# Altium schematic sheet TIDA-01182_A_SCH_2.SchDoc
size 431 x 279 mm; Date: Not shown in title block; ApprovedBy: Not shown in title block; CheckedBy: Not shown in title block; Author: Not shown in title block; CompanyName: Not shown in title block; DrawnBy: Gordon Varney; Engineer: Not shown in title block; Organization: Not shown in title block; Address1: Not shown in title block; Address2: Not shown in title block; Address3: Not shown in title block; Address4: Not shown in title block; DocumentNumber: 1; Revision: Use project parameter SCH_Rev; SheetNumber: 3; SheetTotal: 4; PageSetup: Record=PageOptions¦CenterHorizontal=True¦CenterVertical=True¦PrintScale=0.66¦XCorrection=1.00¦YCorrection=1.00¦PrintKind=0¦BorderSize=5000000¦LeftOffset=0¦BottomOffset=0¦Orientation=2¦PaperLength=1000¦PaperWidth=1000¦Scale=100¦PaperSource=15¦PrintQuality=1200¦MediaType=1¦DitherType=10¦PrintScaleMode=1¦PaperKind=Letter¦PaperIndex=1
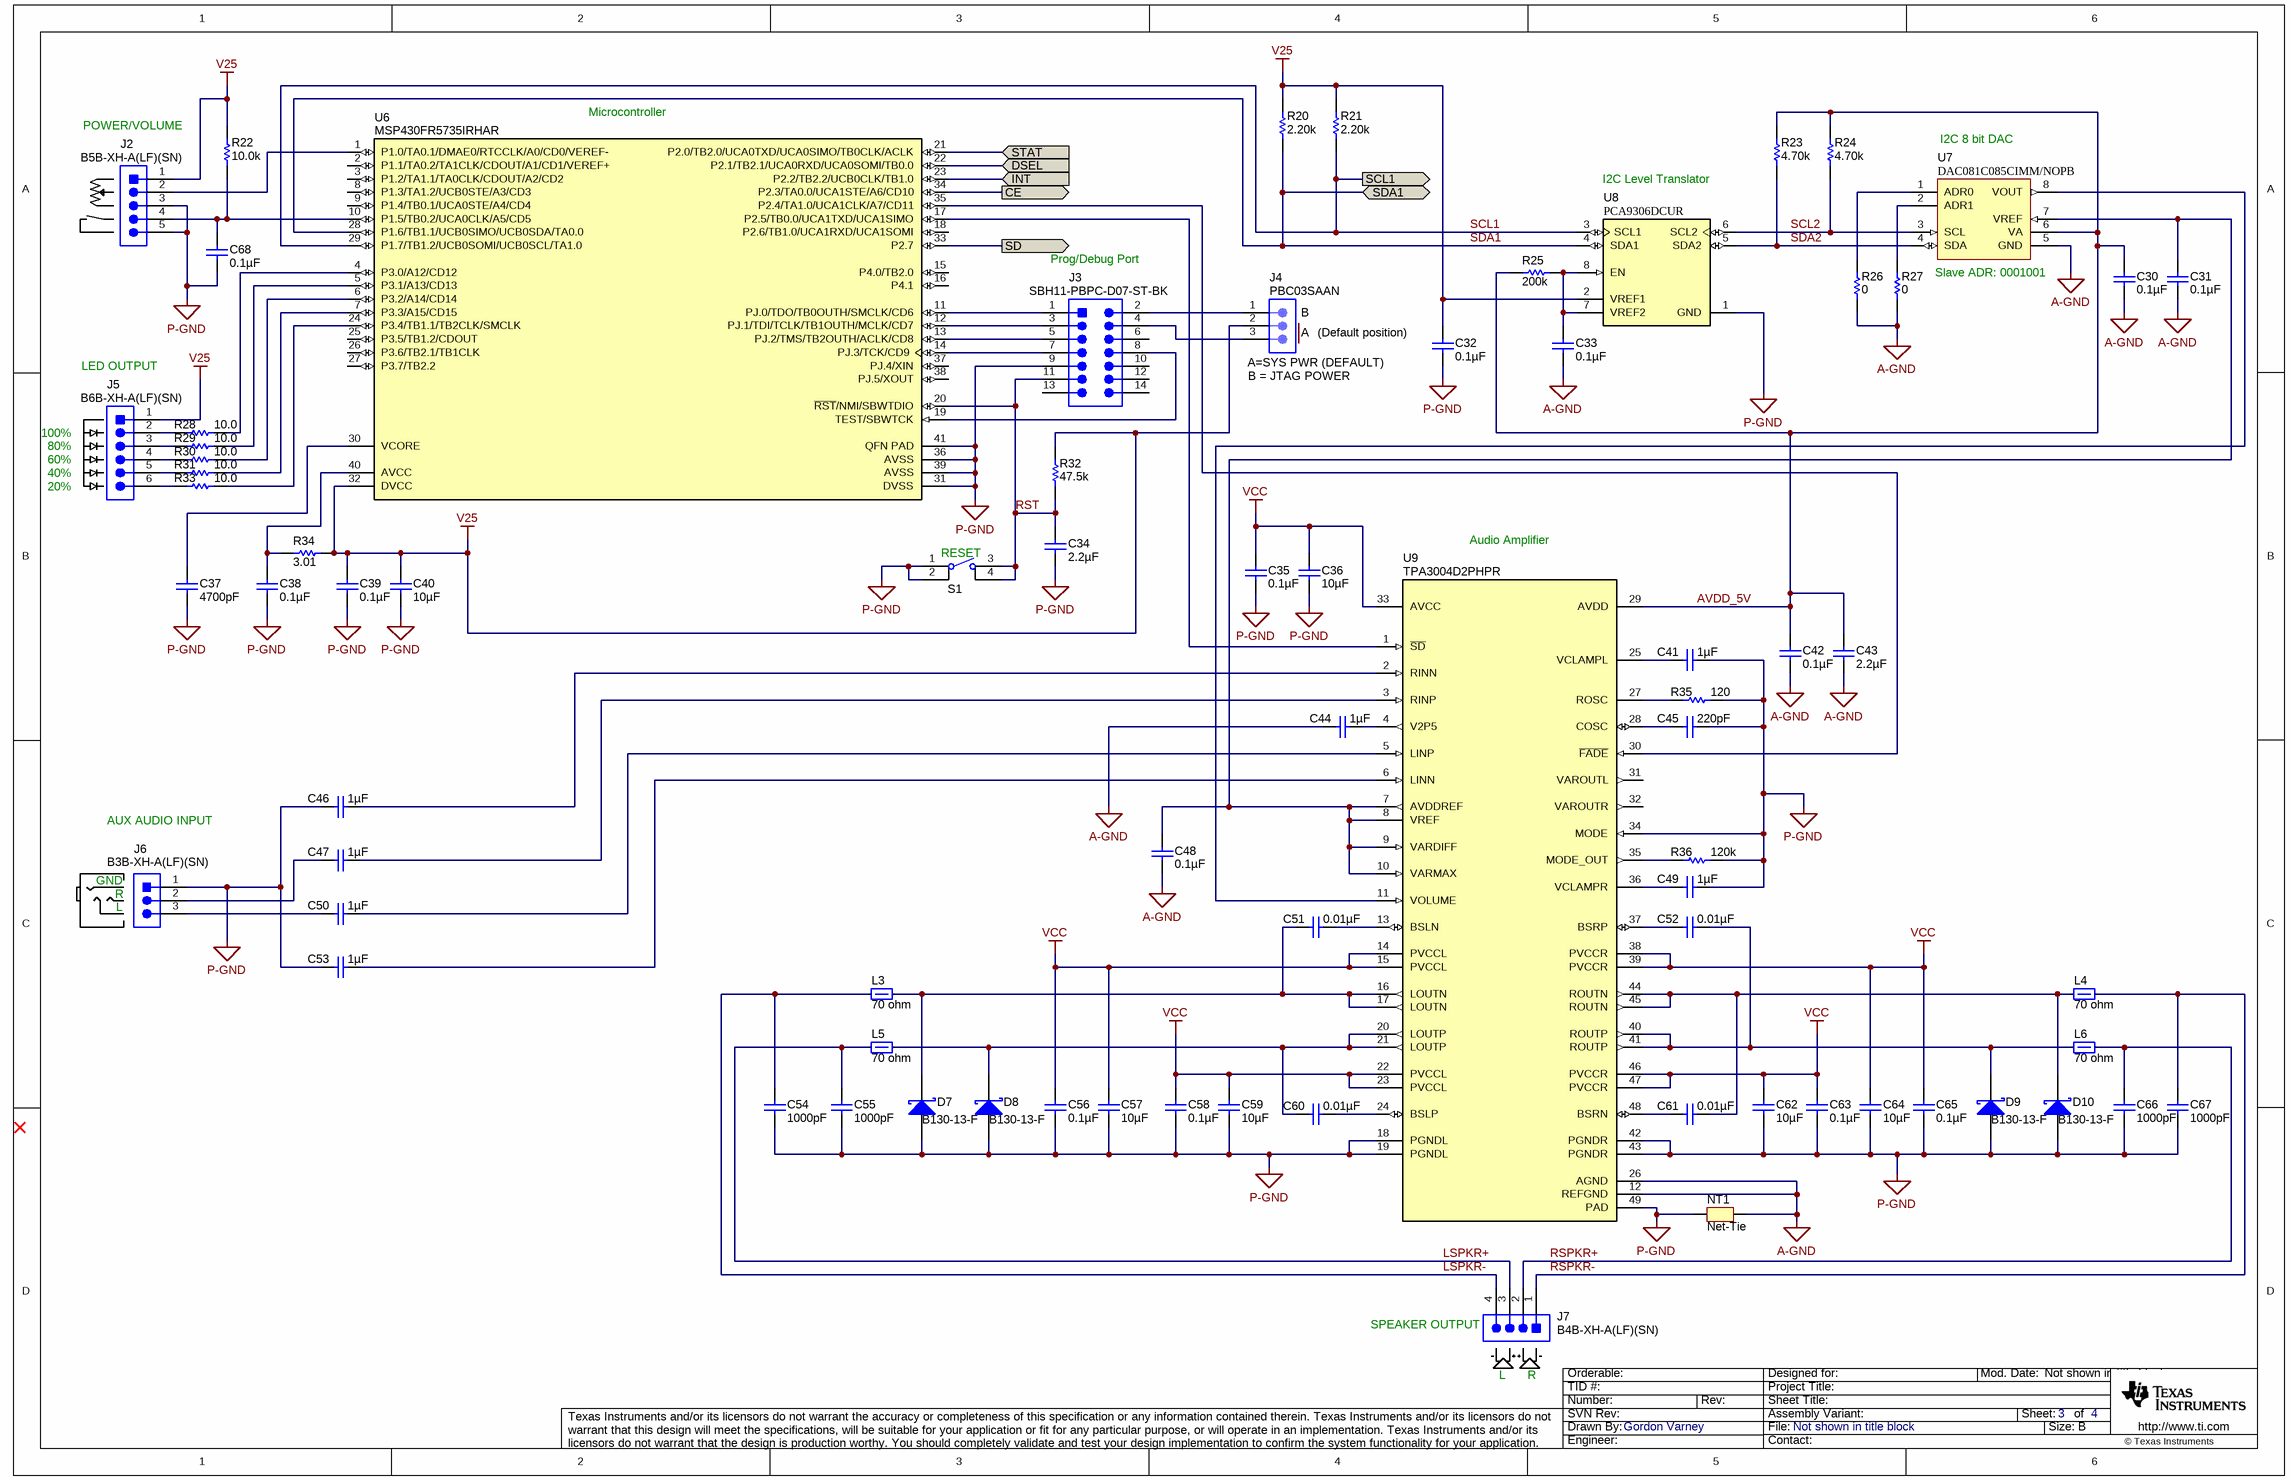
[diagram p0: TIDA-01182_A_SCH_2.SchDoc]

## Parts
C30  ValueDisplayed: 0.1µF  [0603]  (hidden comment: 885012206071)
C31  ValueDisplayed: 0.1µF  [0603]  (hidden comment: 885012206071)
C32  ValueDisplayed: 0.1µF  [0603]  (hidden comment: 885012206071)
C33  ValueDisplayed: 0.1µF  [0603]  (hidden comment: 885012206071)
C34  ValueDisplayed: 2.2µF  [0402]  (hidden comment: GRM155R61C225KE11D)
C35  ValueDisplayed: 0.1µF  [0603]  (hidden comment: 885012206071)
C36  ValueDisplayed: 10µF  [1206]  (hidden comment: 885012208069)
C37  ValueDisplayed: 4700pF  [0402]  (hidden comment: GRM155R71H472KA01D)
C38  ValueDisplayed: 0.1µF  [0603]  (hidden comment: 885012206071)
C39  ValueDisplayed: 0.1µF  [0603]  (hidden comment: 885012206071)
C40  ValueDisplayed: 10µF  [1206]  (hidden comment: 885012208069)
C41  ValueDisplayed: 1µF  [0603]  (hidden comment: GRM188R71C105KA12D)
C42  ValueDisplayed: 0.1µF  [0603]  (hidden comment: 885012206071)
C43  ValueDisplayed: 2.2µF  [0402]  (hidden comment: GRM155R61C225KE11D)
C44  ValueDisplayed: 1µF  [0603]  (hidden comment: GRM188R71C105KA12D)
C45  ValueDisplayed: 220pF  [0402]  (hidden comment: 885012005063)
C46  ValueDisplayed: 1µF  [0603]  (hidden comment: GRM188R71C105KA12D)
C47  ValueDisplayed: 1µF  [0603]  (hidden comment: GRM188R71C105KA12D)
C48  ValueDisplayed: 0.1µF  [0603]  (hidden comment: 885012206071)
C49  ValueDisplayed: 1µF  [0603]  (hidden comment: GRM188R71C105KA12D)
C50  ValueDisplayed: 1µF  [0603]  (hidden comment: GRM188R71C105KA12D)
C51  ValueDisplayed: 0.01µF  [0603]  (hidden comment: C0603C103K5RACTU)
C52  ValueDisplayed: 0.01µF  [0603]  (hidden comment: C0603C103K5RACTU)
C53  ValueDisplayed: 1µF  [0603]  (hidden comment: GRM188R71C105KA12D)
C54  ValueDisplayed: 1000pF  [0603]  (hidden comment: C0603C102K5RACTU)
C55  ValueDisplayed: 1000pF  [0603]  (hidden comment: C0603C102K5RACTU)
C56  ValueDisplayed: 0.1µF  [0603]  (hidden comment: 885012206071)
C57  ValueDisplayed: 10µF  [1206]  (hidden comment: 885012208069)
C58  ValueDisplayed: 0.1µF  [0603]  (hidden comment: 885012206071)
C59  ValueDisplayed: 10µF  [1206]  (hidden comment: 885012208069)
C60  ValueDisplayed: 0.01µF  [0603]  (hidden comment: C0603C103K5RACTU)
C61  ValueDisplayed: 0.01µF  [0603]  (hidden comment: C0603C103K5RACTU)
C62  ValueDisplayed: 10µF  [1206]  (hidden comment: 885012208069)
C63  ValueDisplayed: 0.1µF  [0603]  (hidden comment: 885012206071)
C64  ValueDisplayed: 10µF  [1206]  (hidden comment: 885012208069)
C65  ValueDisplayed: 0.1µF  [0603]  (hidden comment: 885012206071)
C66  ValueDisplayed: 1000pF  [0603]  (hidden comment: C0603C102K5RACTU)
C67  ValueDisplayed: 1000pF  [0603]  (hidden comment: C0603C102K5RACTU)
C68  ValueDisplayed: 0.1µF  [0603]  (hidden comment: 885012206071)
D7  B130-13-F  [SMA]
D8  B130-13-F  [SMA]
D9  B130-13-F  [SMA]
D10  B130-13-F  [SMA]
J2  B5B-XH-A(LF)(SN)  [JST_B5B-XH-A]
J3  SBH11-PBPC-D07-ST-BK  [CONN_SBH11-PBPC-D07-ST-BK]
J4  PBC03SAAN  [PBC03SAAN]
J5  B6B-XH-A(LF)(SN)  [JST_B6B-XH-A]
J6  B3B-XH-A(LF)(SN)  [JST_B3B-XH-A]
J7  B4B-XH-A(LF)(SN)  [JST_B4B-XH-A]
L3  value 70 ohm  [1206]  (hidden comment: 2512067007Y3)
L4  value 70 ohm  [1206]  (hidden comment: 2512067007Y3)
L5  value 70 ohm  [1206]  (hidden comment: 2512067007Y3)
L6  value 70 ohm  [1206]  (hidden comment: 2512067007Y3)
NT1  Net-Tie  [Net-Tie_10mil]  (net tie, no BOM)
R20  ValueDisplayed: 2.20k  [0402]  (hidden comment: CRCW04022K20FKED)
R21  ValueDisplayed: 2.20k  [0402]  (hidden comment: CRCW04022K20FKED)
R22  ValueDisplayed: 10.0k  [0402]  (hidden comment: CRCW040210K0FKED)
R23  ValueDisplayed: 4.70k  [0402]  (hidden comment: ERJ-2RKF4701X)
R24  ValueDisplayed: 4.70k  [0402]  (hidden comment: ERJ-2RKF4701X)
R25  ValueDisplayed: 200k  [0402]  (hidden comment: CRCW0402200KFKED)
R26  ValueDisplayed: 0  [0603]  (hidden comment: ERJ-3GEY0R00V)
R27  ValueDisplayed: 0  [0603]  (hidden comment: ERJ-3GEY0R00V)
R28  ValueDisplayed: 10.0  [0402]  (hidden comment: CRCW040210R0FKED)
R29  ValueDisplayed: 10.0  [0402]  (hidden comment: CRCW040210R0FKED)
R30  ValueDisplayed: 10.0  [0402]  (hidden comment: CRCW040210R0FKED)
R31  ValueDisplayed: 10.0  [0402]  (hidden comment: CRCW040210R0FKED)
R32  ValueDisplayed: 47.5k  [0402]  (hidden comment: CRCW040247K5FKED)
R33  ValueDisplayed: 10.0  [0402]  (hidden comment: CRCW040210R0FKED)
R34  ValueDisplayed: 3.01  [0603]  (hidden comment: CRCW06033R01FKEA)
R35  ValueDisplayed: 120  [0402]  (hidden comment: CRCW0402120RJNED)
R36  ValueDisplayed: 120k  [0402]  (hidden comment: CRCW0402120KFKED)
S1  4-1437565-1  [SW_FSM4JSMA]  (value not drawn)
U6  MSP430FR5735IRHAR  [RHA0040D]
U7  DAC081C085CIMM/NOPB  [MUA08A_N]
U8  PCA9306DCUR  [DCU0008A_N]
U9  TPA3004D2PHPR  [PHP0048D_N]

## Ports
CE, DSEL, INT, SCL1, SD, SDA1, STAT

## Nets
A-GND: C30.2 C31.2 C33.2 C42.2 C43.2 C44.2 C48.2 NT1.2 R26.1 R27.1 U7.5(GND) U9.12(REFGND) U9.26(AGND)
P-GND: C32.2 C34.2 C35.2 C36.2 C37.2 C38.2 C39.2 C40.2 C41.1 C45.2 C46.2 C49.1 C53.2 C54.2 C55.2 C56.2 C57.2 C58.2 C59.2 C62.2 C63.2 C64.2 C65.2 C66.2 C67.2 C68.2 D7.2(A) D8.2(A) D9.2(A) D10.2(A) J2.3 J2.5 J3.9 J6.1 NT1.1 R35.2 R36.2 S1.1 S1.2 U6.31(DVSS) U6.36(AVSS) U6.39(AVSS) U6.41(QFN_PAD) U8.1(GND) U9.18(PGNDL) U9.19(PGNDL) U9.34(MODE) U9.42(PGNDR) U9.43(PGNDR) U9.49(PAD)
V25: C32.1 C39.1 C40.1 J2.1 J4.2 J5.1 R20.2 R21.2 R22.2 R32.2 R34.2 U6.32(DVCC) U8.2(VREF1)
VCC: C35.1 C36.1 C56.1 C57.1 C58.1 C59.1 C62.1 C63.1 C64.1 C65.1 U9.14(PVCCL) U9.15(PVCCL) U9.22(PVCCL) U9.23(PVCCL) U9.33(AVCC) U9.38(PVCCR) U9.39(PVCCR) U9.46(PVCCR) U9.47(PVCCR)
AVDD_5V: C30.1 C42.1 C43.1 R23.2 R24.2 R25.1 U7.6(VA) U9.29(AVDD)
CE: U6.34(P2.3/TA0.0/UCA1STE/A6/CD10) ; port CE
DSEL: U6.22(P2.1/TB2.1/UCA0RXD/UCA0SOMI/TB0.0) ; port DSEL
INT: U6.23(P2.2/TB2.2/UCB0CLK/TB1.0) ; port INT
LSPKR+: C55.1 J7.3 L5.1
LSPKR-: C54.1 J7.4 L3.1
RSPKR+: C66.1 J7.2 L6.2
RSPKR-: C67.1 J7.1 L4.2
RST: C34.1 J3.11 R32.1 S1.3 S1.4 U6.20(~{RST}/NMI/SBWTDIO)
SCL1: R21.1 U6.29(P1.7/TB1.2/UCB0SOMI/UCB0SCL/TA1.0) U8.3(SCL1) ; port SCL1
SCL2: R24.1 U7.3(SCL) U8.6(SCL2)
SD: U6.33(P2.7) ; port SD
SDA1: R20.1 U6.28(P1.6/TB1.1/UCB0SIMO/UCB0SDA/TA0.0) U8.4(SDA1) ; port SDA1
SDA2: R23.1 U7.4(SDA) U8.5(SDA2)
STAT: U6.21(P2.0/TB2.0/UCA0TXD/UCA0SIMO/TB0CLK/ACLK) ; port STAT
NetC31_1: C31.1 C48.1 U7.7(VREF) U9.7(AVDDREF) U9.8(VREF) U9.9(VARDIFF) U9.10(VARMAX)
NetC33_1: C33.1 R25.2 U8.7(VREF2) U8.8(EN)
NetC37_1: C37.1 U6.30(VCORE)
NetC38_1: C38.1 R34.1 U6.40(AVCC)
NetC41_2: C41.2 U9.25(VCLAMPL)
NetC44_1: C44.1 U9.4(V2P5)
NetC45_1: C45.1 U9.28(COSC)
NetC46_1: C46.1 U9.2(RINN)
NetC47_1: C47.1 U9.3(RINP)
NetC47_2: C47.2 J6.2
NetC49_2: C49.2 U9.36(VCLAMPR)
NetC50_1: C50.1 U9.5(LINP)
NetC50_2: C50.2 J6.3
NetC51_1: C51.1 D7.1(K) L3.2 U9.16(LOUTN) U9.17(LOUTN)
NetC51_2: C51.2 U9.13(BSLN)
NetC52_1: C52.1 U9.37(BSRP)
NetC52_2: C52.2 D9.1(K) L6.1 U9.40(ROUTP) U9.41(ROUTP)
NetC53_1: C53.1 U9.6(LINN)
NetC60_1: C60.1 D8.1(K) L5.2 U9.20(LOUTP) U9.21(LOUTP)
NetC60_2: C60.2 U9.24(BSLP)
NetC61_1: C61.1 U9.48(BSRN)
NetC61_2: C61.2 D10.1(K) L4.1 U9.44(ROUTN) U9.45(ROUTN)
NetC68_1: C68.1 J2.4 R22.1 U6.10(P1.5/TB0.2/UCA0CLK/A5/CD5)
NetJ2_2: J2.2 U6.1(P1.0/TA0.1/DMAE0/RTCCLK/A0/CD0/VEREF-)
NetJ3_1: J3.1 U6.11(PJ.0/TDO/TB0OUTH/SMCLK/CD6)
NetJ3_2: J3.2 J4.1
NetJ3_3: J3.3 U6.12(PJ.1/TDI/TCLK/TB1OUTH/MCLK/CD7)
NetJ3_4: J3.4 J4.3
NetJ3_5: J3.5 U6.13(PJ.2/TMS/TB2OUTH/ACLK/CD8)
NetJ3_7: J3.7 U6.14(PJ.3/TCK/CD9)
NetJ3_8: J3.8 U6.19(TEST/SBWTCK)
NetJ5_2: J5.2 R28.1
NetJ5_3: J5.3 R29.1
NetJ5_4: J5.4 R30.1
NetJ5_5: J5.5 R31.1
NetJ5_6: J5.6 R33.1
NetR26_2: R26.2 U7.1(ADR0)
NetR27_2: R27.2 U7.2(ADR1)
NetR28_2: R28.2 U6.4(P3.0/A12/CD12)
NetR29_2: R29.2 U6.5(P3.1/A13/CD13)
NetR30_2: R30.2 U6.6(P3.2/A14/CD14)
NetR31_2: R31.2 U6.7(P3.3/A15/CD15)
NetR33_2: R33.2 U6.24(P3.4/TB1.1/TB2CLK/SMCLK)
NetR35_1: R35.1 U9.27(ROSC)
NetR36_1: R36.1 U9.35(MODE_OUT)
NetU6_17: U6.17(P2.5/TB0.0/UCA1TXD/UCA1SIMO) U9.1(~{SD})
NetU6_35: U6.35(P2.4/TA1.0/UCA1CLK/A7/CD11) U9.30(~{FADE})
NetU7_8: U7.8(VOUT) U9.11(VOLUME)

Not connected (* = marked no-connect by the designer): J3 6 10 12 13 14; U6 2(P1.1/TA0.2/TA1CLK/CDOUT/A1/CD1/VEREF+) 3(P1.2/TA1.1/TA0CLK/CDOUT/A2/CD2) 8(P1.3/TA1.2/UCB0STE/A3/CD3) 9(P1.4/TB0.1/UCA0STE/A4/CD4) 15(P4.0/TB2.0) 16(P4.1) 18(P2.6/TB1.0/UCA1RXD/UCA1SOMI) 25(P3.5/TB1.2/CDOUT) 26(P3.6/TB2.1/TB1CLK) 27(P3.7/TB2.2) 37(PJ.4/XIN) 38(PJ.5/XOUT); U9 31(VAROUTL) 32(VAROUTR)

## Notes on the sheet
- POWER/VOLUME
- (near U6) Microcontroller
- (near U7) I2C 8 bit DAC
- I2C Level Translator
- (near J3) Prog/Debug Port
- (near U7) Slave ADR: 0001001
- LED OUTPUT
- (near J4) A
- (near J4) B
- (near J4) A=SYS PWR (DEFAULT)
- (Default position)
- 100%
- (near J4) B = JTAG POWER
- 40%
- 20%
- 60%
- 80%
- (near S1) RESET
- Audio Amplifier
- AUX AUDIO INPUT
- (near J6) GND
- (near J6) R
- (near J6) L
- (near J7) SPEAKER OUTPUT
- L
- R

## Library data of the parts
C30-C33 C35 C38 C39 C42 C48 C56 C58 C63 C65 C68 = 885012206071: CAP, CERM, 0.1 µF, 25 V, +/- 10%, X7R, 0603; Manufacturer: Wurth Elektronik; Polarized: N; CompType: Capacitor; Value: 0.1uF; U/M: EA; Cap_F: 0.0000001; Tolerance_%: 10; Value1: Unknown; VDC_V: 25; Value2: 25V; TaMin_C: -55; TaMax_C: 125; SizeArea_mm2: 1.28; SizeAreaWB_mm2: 4.68; SizeX_mm: 1.6; SizeY_mm: 0.8; SizeZ_mm: 1; AEC Category: Q200
C34 C43 = GRM155R61C225KE11D: CAP, CERM, 2.2 µF, 16 V, +/- 10%, X5R, 0402; Manufacturer: MuRata; Polarized: N; CompType: Capacitor; Value: 2.2uF; U/M: EA; Cap_F: 0.0000022; Tolerance_%: 10; Value1: Unknown; VDC_V: 16; Value2: 16V; TaMin_C: -55; TaMax_C: 85; SizeArea_mm2: 0.5; SizeAreaWB_mm2: 3; SizeX_mm: 1; SizeZ_mm: 0.6; AEC Category: Q200
C36 C40 C57 C59 C62 C64 = 885012208069: CAP, CERM, 10 µF, 25 V, +/- 10%, X7R, 1206; Manufacturer: Wurth Elektronik; Polarized: N; CompType: Capacitor; Value: 10uF; U/M: EA; Cap_F: 0.00001; Tolerance_%: 10; Value1: Unknown; VDC_V: 25; Value2: 25V; TaMin_C: -55; TaMax_C: 125; SizeArea_mm2: 5.12; SizeAreaWB_mm2: 10.92; SizeX_mm: 3.2; SizeY_mm: 1.6; SizeZ_mm: 1.35; AEC Category: Q200
C37 = GRM155R71H472KA01D: CAP, CERM, 4700 pF, 50 V, +/- 10%, X7R, 0402; Manufacturer: MuRata; Polarized: N; CompType: Capacitor; Value: 4700pF; U/M: EA; Cap_F: 0.0000000047; Tolerance_%: 10; Value1: Unknown; VDC_V: 50; Value2: 50V; TaMin_C: -55; TaMax_C: 125; SizeArea_mm2: 0.5; SizeAreaWB_mm2: 3; SizeX_mm: 1; SizeZ_mm: 0.6; AEC Category: Q200
C41 C44 C46 C47 C49 C50 C53 = GRM188R71C105KA12D: CAP, CERM, 1 µF, 16 V, +/- 10%, X7R, 0603; Manufacturer: MuRata; Polarized: N; CompType: Capacitor; Value: 1uF; U/M: EA; Cap_F: 0.000001; Tolerance_%: 10; ESR_ohm: 0.011; Value1: 0.011 ohm; VDC_V: 16; Value2: 16V; TaMin_C: -55; TaMax_C: 125; SizeArea_mm2: 1.28; SizeAreaWB_mm2: 4.68; SizeX_mm: 1.6; SizeY_mm: 0.8; SizeZ_mm: 1; AEC Category: Q200
C45 = 885012005063: CAP, CERM, 220 pF, 50 V, +/- 5%, C0G/NP0, 0402; Manufacturer: Wurth Elektronik; Polarized: N; CompType: Capacitor; Value: 220pF; U/M: EA; Cap_F: 0.00000000022; Tolerance_%: 5; Value1: Unknown; VDC_V: 50; Value2: 50V; TaMin_C: -55; TaMax_C: 125; SizeArea_mm2: 0.5; SizeAreaWB_mm2: 3; SizeX_mm: 1; SizeZ_mm: 0.6; AEC Category: Q200
C51 C52 C60 C61 = C0603C103K5RACTU: CAP, CERM, 0.01 µF, 50 V, +/- 10%, X7R, 0603; Manufacturer: Kemet; Polarized: N; CompType: Capacitor; Value: 0.01uF; U/M: EA; Cap_F: 0.00000001; Tolerance_%: 10; Value1: Unknown; VDC_V: 50; Value2: 50V; TaMin_C: -55; TaMax_C: 125; SizeArea_mm2: 1.28; SizeAreaWB_mm2: 4.68; SizeX_mm: 1.6; SizeY_mm: 0.8; SizeZ_mm: 1; AEC Category: Q200
C54 C55 C66 C67 = C0603C102K5RACTU: CAP, CERM, 1000 pF, 50 V, +/- 10%, X7R, 0603; Manufacturer: Kemet; Polarized: N; CompType: Capacitor; Value: 1000pF; U/M: EA; Cap_F: 0.000000001; Tolerance_%: 10; Value1: Unknown; VDC_V: 50; Value2: 50V; TaMin_C: -55; TaMax_C: 125; SizeArea_mm2: 1.28; SizeAreaWB_mm2: 4.68; SizeX_mm: 1.6; SizeY_mm: 0.8; SizeZ_mm: 1; AEC Category: Q200
D7-D10 = B130-13-F: Diode, Schottky, 30 V, 1 A, SMA; Manufacturer: Diodes Inc.; U/M: EA; Vf_V: 0.5; Value: 30V; Value1: 1A; Value2: 0.5V; Io_A: 1; Vr_V: 30; TJmax_C: 150; RJC_CperW: 20; SizeAreaWB_mm2: 37.3428; SizeArea_mm2: 16.3228; SizeX_mm: 5.59; SizeY_mm: 2.92; SizeZ_mm: 2.87; AEC Category: Q101
J2 = B5B-XH-A(LF)(SN): Header(shrouded), 2.5mm, 5x1, Tin, TH; Manufacturer: JST Manufacturing; SymbolCreator: a0412235; Pitch_mm: 2.5; Gender: Male; Shrouded: Y; Row_Count: 1; Current_A: 3; Voltage_V: 250
J3 = SBH11-PBPC-D07-ST-BK: Header (shrouded), 100 mil, 7x2, Gold, TH; Manufacturer: Sullins Connector Solutions; SymbolCreator: a0412235
J4 = PBC03SAAN: Header, 100mil, 3x1, Gold, TH; Manufacturer: Sullins Connector Solutions
J5 = B6B-XH-A(LF)(SN): Header (Shrouded), 2.5mm, 6x1, Tin, TH; Manufacturer: JST Manufacturing; SymbolCreator: a0412235; Pitch_mm: 2.5; Gender: Male; Shrouded: Y; Row_Count: 1; Current_A: 3; Voltage_V: 250
J6 = B3B-XH-A(LF)(SN): Header (Shrouded), 2.5mm, 3x1, Tin, TH; Manufacturer: JST Manufacturing; SymbolCreator: a0799628; Pitch_mm: 2.5; Gender: Male; Shrouded: Y; Row_Count: 1; Current_A: 3; Voltage_V: 250
J7 = B4B-XH-A(LF)(SN): Header (Shrouded), 2.5mm, 4x1, Tin, TH; Manufacturer: JST Manufacturing; SymbolCreator: a0412235; Pitch_mm: 2.5; Gender: Male; Shrouded: Y; Row_Count: 1; Current_A: 3; Voltage_V: 250
L3-L6 = 2512067007Y3: Ferrite Bead, 70 ohm @ 100 MHz, 3 A, 1206; Manufacturer: Fair-Rite Products; Imax_A: 3; DCR_ohm: 0.04; Value1: 0.04 ohm; Value2: 3A; ZTyp@100MHz_Ohm: 70
NT1 = Net-Tie: Single point connection between nets.; SymbolCreator: codlsc
R20 R21 = CRCW04022K20FKED: RES, 2.20 k, 1%, 0.063 W, 0402; Manufacturer: Vishay-Dale; CompType: Resistor; Value: 2.20k; Res_ohm: 2200; Value_Code: 2k20; Tolerance_%: 1; Power_W: 0.063; Value2: 0.063W; TempCo: 100 ppm/C; SizeArea_mm2: 0.5; SizeZ_mm: 0.6; U/M: EA; AEC Category: Q200
R22 = CRCW040210K0FKED: RES, 10.0 k, 1%, 0.063 W, 0402; Manufacturer: Vishay-Dale; CompType: Resistor; Value: 10.0k; Res_ohm: 10000; Value_Code: 10k0; Tolerance_%: 1; Power_W: 0.063; Value2: 0.063W; VDC_V: 50; TempCo: 100 ppm/C; EIA_Code: E96; U/M: EA; SizeArea_mm2: 0.5; SizeZ_mm: 0.6; AEC Category: Q200
R23 R24 = ERJ-2RKF4701X: RES, 4.70 k, 1%, 0.1 W, 0402; Manufacturer: Panasonic; CompType: Resistor; Value: 4.70k; Res_ohm: 4700; Value_Code: 4k70; Tolerance_%: 1; Power_W: 0.1; Value2: 0.1W; VDC_V: 50; TempCo: 100 ppm/C; SizeArea_mm2: 0.5; SizeZ_mm: 0.6; U/M: EA; AEC Category: Q200
R25 = CRCW0402200KFKED: RES, 200 k, 1%, 0.063 W, 0402; Manufacturer: Vishay-Dale; CompType: Resistor; Value: 200k; Res_ohm: 200000; Tolerance_%: 1; Power_W: 0.063; Value2: 0.063W; VDC_V: 50; TempCo: 100 ppm/C; SizeArea_mm2: 0.5; SizeZ_mm: 0.6; EIA_Code: E96; U/M: EA; AEC Category: Q200
R26 R27 = ERJ-3GEY0R00V: RES, 0, 5%, 0.1 W, 0603; Manufacturer: Panasonic; CompType: Resistor; Value: 0; Value_Code: 0000; Tolerance_%: 5; Power_W: 0.1; Value2: 0.1W; VDC_V: 50; TempCo: 600 ppm/C; SizeArea_mm2: 1.28; SizeX_mm: 1.6; SizeY_mm: 0.8; SizeZ_mm: 1; EIA_Code: E24; U/M: EA; AEC Category: Q200
R28-R31 R33 = CRCW040210R0FKED: RES, 10.0, 1%, 0.063 W, 0402; Manufacturer: Vishay-Dale; CompType: Resistor; Value: 10.0; Res_ohm: 10; Value_Code: 10R0; Tolerance_%: 1; Power_W: 0.063; Value2: 0.063W; VDC_V: 50; TempCo: 100 ppm/C; SizeArea_mm2: 0.5; SizeZ_mm: 0.6; EIA_Code: E96; U/M: EA; AEC Category: Q200
R32 = CRCW040247K5FKED: RES, 47.5 k, 1%, 0.063 W, 0402; Manufacturer: Vishay-Dale; CompType: Resistor; Value: 47.5k; Res_ohm: 47500; Value_Code: 47k5; Tolerance_%: 1; Power_W: 0.063; Value2: 0.063W; VDC_V: 50; TempCo: 100 ppm/C; SizeArea_mm2: 0.5; SizeZ_mm: 0.6; EIA_Code: E96; U/M: EA; AEC Category: Q200
R34 = CRCW06033R01FKEA: RES, 3.01, 1%, 0.1 W, 0603; Manufacturer: Vishay-Dale; CompType: Resistor; Value: 3.01; Value_Code: 3R01; Tolerance_%: 1; Power_W: 0.1; Value2: 0.1W; VDC_V: 75; TempCo: 100 ppm/C; SizeArea_mm2: 1.28; SizeX_mm: 1.6; SizeY_mm: 0.8; EIA_Code: E96; U/M: EA; AEC Category: Q200
R35 = CRCW0402120RJNED: RES, 120, 5%, 0.063 W, 0402; Manufacturer: Vishay-Dale; CompType: Resistor; Value: 120; Value_Code: 120R; Tolerance_%: 5; Power_W: 0.063; Value2: 0.063W; VDC_V: 50; TempCo: 200 ppm/C; SizeArea_mm2: 0.5; SizeX_mm: 1; SizeZ_mm: 0.6; EIA_Code: E24; U/M: EA; AEC Category: Q200
R36 = CRCW0402120KFKED: RES, 120 k, 1%, 0.063 W, 0402; Manufacturer: Vishay-Dale; CompType: Resistor; Value: 120k; Res_ohm: 120000; Tolerance_%: 1; Power_W: 0.063; Value2: 0.063W; VDC_V: 50; TempCo: 100 ppm/C; SizeArea_mm2: 0.5; SizeZ_mm: 0.6; U/M: EA; AEC Category: Q200
S1 = 4-1437565-1: Switch, Tactile, SPST-NO, 0.05A, 12V, SMT; Manufacturer: TE Connectivity; SymbolCreator: a0412235; VDC_V: 12; SwitchFunction: Off-Mom; PositionCount: 1; CurrentRating_mA: 50
U6 = MSP430FR5735IRHAR: 24 MHz Mixed Signal Microcontroller, 1024 B SRAM and 33 GPIOs, -40 to 85 degC, 40-pin QFN (RHA), Green (RoHS & no Sb/Br); Alternate Manufacturer: Texas Instruments; Alternate PartNumber: Equivalent; ADC: 10-bit SAR; ADC Channels: 14; Brown Out Reset: Yes; DMA: 3; FRAM(KB): 8; Frequency(MHz): 24; GPIO: 33; Multiplier: 32x32; Pin/Package: 38TSSOP, 40VQFN; SRAM(B): 1024; SubFamily: FRAM Series; Timers - 16-bit: 5; USCI_A (UART/LIN/IrDA/SPI): 2; USCI_B (I2C & SPI): 1
U7 = DAC081C085CIMM/NOPB: 8-Bit Micro Power Digital-to-Analog Converter with an I2C-Compatible Interface and External Reference, 8-pin Mini SOIC, Pb-Free; Manufacturer: Texas Instruments; PackageTopMarking: ZXTT*X92C; PowerWise: N; CompType: D/A Converter
U8 = PCA9306DCUR: Dual Bi-Directional I2C-Bus and SMBus Voltage Level-Translator, 0 to 5.5 V, -40 to 85 degC, 8-pin US8 (DCU), Green (RoHS & no Sb/Br); Manufacturer: Texas Instruments; Alternate PartNumber: Equivalent; SubFamily: I2C Special Function; No. of Outputs: 2; tpd max(ns): 1.5; fSCLK(Max)(MHz): 400; Function: Voltage Translator; Vcc range(V): 0 to 5.5; Enable Pin: Yes; Rating: Catalog
U9 = TPA3004D2PHPR: 12-W STEREO CLASS-D AUDIO POWER AMPLIFIER WITH DC VOLUME CONTROL , PHP0048D; Manufacturer: Texas Instruments; SymbolCreator: Altium; SizeArea_mm2: 81; SizeAreaWB_mm2: 121; SizeX_mm: 9; SizeZ_mm: 1.2; CompType: IC; U/M: EA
